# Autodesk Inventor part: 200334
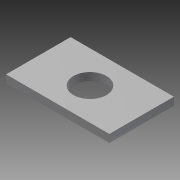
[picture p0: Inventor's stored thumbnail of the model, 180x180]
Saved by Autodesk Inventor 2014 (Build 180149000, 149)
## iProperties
Created: 2007-12
Part Number: 200334
Document SubType Name: Modeling
Designer: MM
Density: 7.85 g/cm^3
Mass: 20.5196 g
Surface Area: 22.5328 cm^2
Volume: 2.61396 cm^3
Material: Steel
Description: SPACER
Appearance: Steel
Component Category: Lower Component
Author: MM
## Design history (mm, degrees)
sketch "Sketch1"
  geometry: L1 (-20, -12.5)-(20, -12.5); L2 (20, -12.5)-(20, 12.5); L3 (20, 12.5)-(-20, 12.5); L4 (-20, 12.5)-(-20, -12.5); C1 r 6.4 at (0, 0); 1 further point
  constraints: 8 end point, 2 parallel, 1 centre point, 1 coincident, 1 horizontal, 1 perpendicular
  dimensions: "d0" = 12.8 diameter of C1; "d1" = 20 distance from line of point (0, 0) L4 (= 0.5 x d2); "d2" = 40 distance of L2.end L3.end; "d3" = 25 distance of L3.end L1.start; "d4" = 12.5 distance from line of L3 point (0, 0) (= 0.5 x d3)
extrude "Extrusion1" new body sketch "Sketch1" distance "d5" = 3; taper "d6" = 0 deg
body "Solid1"
